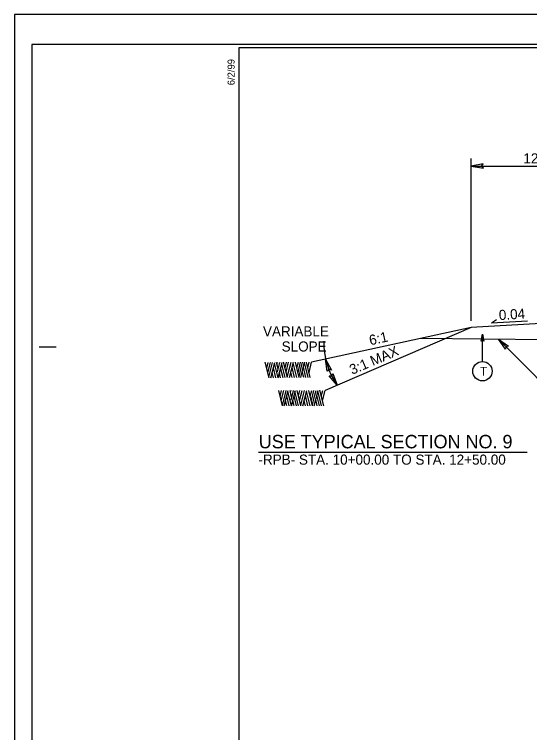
# Model space of a CAD drawing. Extents: x 573748 to 574632, y -54663 to -53209.
# Drawn here: x 573944.2 to 574020.8, y -54255.6 to -54148.7 of the extents above; entities that cross this region are included whole.
import ezdxf

# ---------------------------------------------------------------- set-up
doc = ezdxf.new("R2010")
doc.units = 0
for name, color, linetype in [('Prop Dimension', 7, 'Continuous'), ('Prop Dimension Text', 7, 'Continuous'), ('Prop Terminator CELL', 7, 'Continuous'), ('Sheet Cutting Line CELL', 7, 'Continuous'), ('Sheet Plot Border Inside CELL', 7, 'Continuous'), ('Sheet Plot Border Outside CELL', 7, 'Continuous'), ('Sheet Typical CELL', 7, 'Continuous'), ('Typical Arrow Superelevation CELL', 7, 'Continuous'), ('Typical Hinge Slope Arterial CELL', 7, 'Continuous'), ('Typical ID Circle CELL', 7, 'Continuous'), ('Typical Pavement Slope CELL', 7, 'Continuous'), ('Typical Slope Point Local CELL', 7, 'Continuous'), ('Typical Terminator CELL', 7, 'Continuous'), ('Typical Text General CELL', 7, 'Continuous'), ('Typical Text ID Circle CELL', 7, 'Continuous')]:
    doc.layers.add(name, color=color, linetype=linetype)

msp = doc.modelspace()

# ---------------------------------------------------------------- linework, layer by layer
at = {"layer": 'Prop Dimension'}
for p, q in [((574012.15, -54194.26), (574012.15, -54170.11)), ((574012.15, -54171.24), (574030.15, -54171.24))]:
    msp.add_line(p, q, dxfattribs=at)
msp.add_lwpolyline([(574028.37, -54208.24), (574027.42, -54208.24), (574016.19, -54197.01)], dxfattribs=at)
msp.add_arc((574001.32, -54197.47), 11.12, 179.1001, 214.9438, dxfattribs=at)
at = {"layer": 'Prop Terminator CELL'}
for points in [[(574013.94, -54170.91), (574012.15, -54171.24), (574013.96, -54171.54), (574013.73, -54171.22)], [(574017.25, -54198.5), (574016.19, -54197.01), (574017.7, -54198.06), (574017.31, -54198.13)], [(573990.72, -54201.78), (573990.48, -54199.97), (573991.33, -54201.6), (573990.95, -54201.48)], [(573991.54, -54202.13), (573992.2, -54203.84), (573991, -54202.45), (573991.39, -54202.48)]]:
    msp.add_lwpolyline(points, close=True, dxfattribs=at)
at = {"layer": 'Sheet Cutting Line CELL'}
for p, q in [((574280.97, -54148.66), (573944.17, -54148.66)), ((573944.17, -54148.66), (573944.17, -54368.66))]:
    msp.add_line(p, q, dxfattribs=at)
at = {"layer": 'Sheet Plot Border Inside CELL'}
msp.add_lwpolyline([(574280.07, -54153.15), (573946.77, -54153.15), (573946.77, -54364.17), (574280.07, -54364.17)], close=True, dxfattribs=at)
at = {"layer": 'Sheet Plot Border Outside CELL'}
msp.add_lwpolyline([(574280.97, -54148.66), (573944.17, -54148.66), (573944.17, -54368.66), (574280.97, -54368.66)], close=True, dxfattribs=at)
at = {"layer": 'Sheet Typical CELL'}
msp.add_line((573947.87, -54198.16), (573950.37, -54198.16), dxfattribs=at)
msp.add_lwpolyline([(574277.57, -54153.66), (573977.57, -54153.66), (573977.57, -54363.66), (574277.57, -54363.66)], close=True, dxfattribs=at)
at = {"layer": 'Typical Arrow Superelevation CELL'}
for q in [(574015.9, -54194.08), (574020.52, -54194.25)]:
    msp.add_line((574015.14, -54194.58), q, dxfattribs=at)
at = {"layer": 'Typical Hinge Slope Arterial CELL'}
for q in [(573988.39, -54200.42), (573990.39, -54204.62)]:
    msp.add_line((574012.15, -54195.26), q, dxfattribs=at)
at = {"layer": 'Typical ID Circle CELL'}
msp.add_line((574013.81, -54200.33), (574013.81, -54196.24), dxfattribs=at)
msp.add_circle((574013.81, -54201.77), 1.44, dxfattribs=at)
at = {"layer": 'Typical Pavement Slope CELL'}
for p, q in [((574024.15, -54194.56), (574012.15, -54195.26)), ((574086.92, -54197.74), (574004.63, -54196.89))]:
    msp.add_line(p, q, dxfattribs=at)
at = {"layer": 'Typical Slope Point Local CELL'}
for p, q in [((573982.07, -54202.74), (573981.5, -54200.44)), ((573981.72, -54201.32), (573981.93, -54200.45)), ((573981.88, -54202.01), (573982.27, -54200.45)), ((573982.05, -54202.67), (573982.6, -54200.45)), ((573982.33, -54202.74), (573982.9, -54200.45)), ((573983.41, -54202.74), (573982.87, -54200.57)), ((573983.42, -54201.42), (573983.18, -54200.45)), ((573983.29, -54200.53), (573983.32, -54200.42)), ((573983.33, -54201.88), (573983.69, -54200.45)), ((573983.33, -54200.56), (573983.36, -54200.45)), ((573983.42, -54202.74), (573983.99, -54200.45)), ((573984.46, -54202.7), (573983.92, -54200.53)), ((573984.79, -54202.7), (573984.23, -54200.42)), ((573984.44, -54201.26), (573984.65, -54200.42)), ((573984.61, -54201.93), (573984.98, -54200.42)), ((573984.78, -54202.64), (573985.33, -54200.42)), ((573985.11, -54202.7), (573985.68, -54200.42)), ((573986.19, -54202.7), (573985.65, -54200.53)), ((573986.56, -54202.7), (573986, -54200.42)), ((573986.21, -54201.29), (573986.42, -54200.42)), ((573986.37, -54201.95), (573986.75, -54200.42)), ((573986.79, -54201.49), (573987.05, -54200.42)), ((573986.79, -54202.7), (573987.36, -54200.42)), ((573987.89, -54202.7), (573987.34, -54200.49)), ((573988.19, -54202.7), (573987.63, -54200.41)), ((573987.84, -54201.29), (573988.05, -54200.42)), ((573988.01, -54201.97), (573988.39, -54200.42)), ((573983.06, -54202.74), (573982.7, -54201.26)), ((573983.4, -54201.29), (573983.42, -54201.2)), ((573984.15, -54202.74), (573983.79, -54201.26)), ((573985.85, -54202.7), (573985.48, -54201.22)), ((573986.52, -54202.56), (573986.79, -54201.49)), ((573987.55, -54202.7), (573987.18, -54201.15)), ((573982.7, -54202.74), (573982.52, -54201.97)), ((573983.79, -54202.74), (573983.61, -54201.97)), ((573985.5, -54202.7), (573985.31, -54201.91)), ((573987.24, -54202.7), (573987.01, -54201.8)), ((573984.06, -54206.94), (573983.5, -54204.64)), ((573983.71, -54205.52), (573983.92, -54204.65)), ((573983.88, -54206.2), (573984.27, -54204.65)), ((573984.05, -54206.86), (573984.59, -54204.65)), ((573984.32, -54206.94), (573984.89, -54204.65)), ((573985.4, -54206.94), (573984.87, -54204.77)), ((573985.42, -54205.61), (573985.18, -54204.65)), ((573985.29, -54204.72), (573985.31, -54204.62)), ((573985.33, -54206.08), (573985.68, -54204.65)), ((573985.33, -54204.76), (573985.35, -54204.65)), ((573985.41, -54206.94), (573985.98, -54204.65)), ((573986.45, -54206.9), (573985.92, -54204.73)), ((573986.79, -54206.9), (573986.23, -54204.62)), ((573986.44, -54205.46), (573986.64, -54204.62)), ((573986.6, -54206.12), (573986.97, -54204.62)), ((573986.77, -54206.83), (573987.32, -54204.62)), ((573987.11, -54206.9), (573987.68, -54204.62)), ((573988.19, -54206.9), (573987.65, -54204.72)), ((573988.55, -54206.9), (573987.99, -54204.62)), ((573988.2, -54205.49), (573988.42, -54204.62)), ((573988.37, -54206.15), (573988.75, -54204.62)), ((573988.79, -54205.68), (573989.05, -54204.62)), ((573988.79, -54206.9), (573989.35, -54204.62)), ((573989.89, -54206.9), (573989.34, -54204.68)), ((573990.19, -54206.9), (573989.63, -54204.6)), ((573989.83, -54205.48), (573990.05, -54204.62)), ((573990.01, -54206.17), (573990.39, -54204.62)), ((573985.05, -54206.94), (573984.69, -54205.45)), ((573985.39, -54205.49), (573985.42, -54205.4)), ((573986.14, -54206.94), (573985.78, -54205.45)), ((573987.84, -54206.9), (573987.48, -54205.41)), ((573988.52, -54206.76), (573988.79, -54205.68)), ((573989.55, -54206.9), (573989.17, -54205.34)), ((573984.7, -54206.94), (573984.52, -54206.17)), ((573985.79, -54206.94), (573985.61, -54206.17)), ((573987.5, -54206.9), (573987.31, -54206.11)), ((573989.23, -54206.9), (573989.01, -54206))]:
    msp.add_line(p, q, dxfattribs=at)
at = {"layer": 'Typical Terminator CELL'}
msp.add_lwpolyline([(574013.63, -54197.3), (574013.81, -54196.24), (574014, -54197.3), (574013.81, -54197.17)], close=True, dxfattribs=at)
at = {"layer": 'Typical Text General CELL'}
msp.add_line((573980.49, -54213.8), (574020.48, -54213.8), dxfattribs=at)

# ---------------------------------------------------------------- texts
at = {"layer": 'Prop Dimension Text'}
msp.add_text("12'", height=1.5, dxfattribs=at).set_placement((574019.9, -54170.84))
for s, rotation, p in [('0.04', 3.5612, (574016.3, -54194.17)), ('6:1', 12.2721, (573997.13, -54197.92)), ('3:1 MAX', 23.1063, (573994.42, -54202.32))]:
    msp.add_text(s, height=1.5, rotation=rotation, dxfattribs=at).set_placement(p)
at = {"layer": 'Sheet Typical CELL'}
msp.add_text('6/2/99', height=1.05, rotation=90, dxfattribs=at).set_placement((573976.94, -54159.21))
at = {"layer": 'Typical Text General CELL'}
for s, height, p in [('VARIABLE', 1.5, (573981.16, -54196.59)), ('SLOPE', 1.5, (573983.94, -54198.84)), ('USE TYPICAL SECTION NO. 9', 2, (573980.53, -54213.25)), ('-RPB- STA. 10+00.00 TO STA. 12+50.00', 1.5, (573980.49, -54215.68))]:
    msp.add_text(s, height=height, dxfattribs=at).set_placement(p)
at = {"layer": 'Typical Text ID Circle CELL'}
msp.add_text('T', height=1.29, dxfattribs=at).set_placement((574013.46, -54202.41))

doc.saveas('drawing.dxf')
